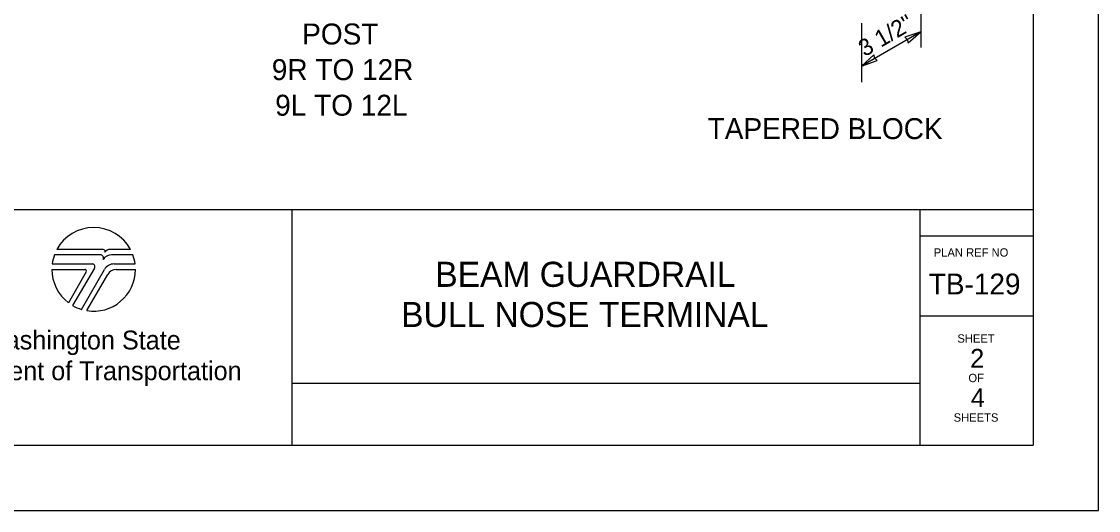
# Model space of a CAD drawing. Extents: x 1312564.2 to 1312581.5, y 1207298.4 to 1207352.6.
# Drawn here: x 1312576.33 to 1312581.48, y 1207312.82 to 1207315.16 of the extents above; entities that cross this region are included whole.
import ezdxf

# ---------------------------------------------------------------- set-up
doc = ezdxf.new("R2010")
doc.units = 0
for name, color, linetype in [('Level 1', 7, 'Continuous'), ('Level 15', 7, 'Continuous'), ('Level 2', 7, 'Continuous'), ('Level 20', 7, 'Continuous'), ('Level 36', 7, 'Continuous'), ('Level 63', 7, 'Continuous'), ('SH_GI_SheetTextInCells', 7, 'Continuous')]:
    doc.layers.add(name, color=color, linetype=linetype)

msp = doc.modelspace()

# ---------------------------------------------------------------- linework, layer by layer
at = {"layer": 'Level 1'}
for p, q in [((1312581.1655, 1207323.5084), (1312581.1655, 1207313.1334)), ((1312565.4155, 1207314.2593), (1312581.1655, 1207314.2593)), ((1312577.621, 1207314.2593), (1312577.621, 1207313.1334)), ((1312580.6233, 1207314.2593), (1312580.6233, 1207313.1334)), ((1312580.6233, 1207314.1342), (1312581.1655, 1207314.1342)), ((1312580.6233, 1207313.751), (1312581.1655, 1207313.751)), ((1312577.621, 1207313.4289), (1312580.6233, 1207313.4289)), ((1312565.4155, 1207313.1334), (1312581.1655, 1207313.1334))]:
    msp.add_line(p, q, dxfattribs=at)
at = {"layer": 'Level 15'}
for p, q in [((1312580.628, 1207315.3175), (1312580.628, 1207315.0345)), ((1312580.344, 1207315.1499), (1312580.344, 1207314.8684)), ((1312580.628, 1207315.1095), (1312580.344, 1207314.9455))]:
    msp.add_line(p, q, dxfattribs=at)
for points in [[(1312580.628, 1207315.1095), (1312580.5521, 1207315.0835), (1312580.563, 1207315.072), (1312580.5676, 1207315.0568)], [(1312580.344, 1207314.9455), (1312580.4199, 1207314.9715), (1312580.409, 1207314.9831), (1312580.4045, 1207314.9983)]]:
    msp.add_lwpolyline(points, close=True, dxfattribs=at)
at = {"layer": 'Level 2'}
msp.add_lwpolyline([(1312564.478, 1207312.8209), (1312581.478, 1207312.8209), (1312581.478, 1207323.8209), (1312564.478, 1207323.8209)], close=True, dxfattribs=at)
at = {"layer": 'Level 63'}
for p, q in [((1312576.7049, 1207314.0428), (1312576.4852, 1207314.0428)), ((1312576.7185, 1207314.0688), (1312576.497, 1207314.0688)), ((1312576.8485, 1207314.0688), (1312576.7506, 1207314.0688)), ((1312576.7585, 1207314.0428), (1312576.7584, 1207314.0428)), ((1312576.8603, 1207314.0428), (1312576.7585, 1207314.0428)), ((1312576.4745, 1207313.9994), (1312576.6651, 1207313.9994)), ((1312576.7713, 1207313.9994), (1312576.871, 1207313.9994)), ((1312576.4727, 1207313.9734), (1312576.6303, 1207313.9734)), ((1312576.6374, 1207313.9611), (1312576.5519, 1207313.8141)), ((1312576.6765, 1207313.9797), (1312576.5722, 1207313.8006)), ((1312576.6144, 1207313.7821), (1312576.7244, 1207313.9724)), ((1312576.6399, 1207313.7762), (1312576.7397, 1207313.949)), ((1312576.7809, 1207313.9728), (1312576.8727, 1207313.9728))]:
    msp.add_line(p, q, dxfattribs=at)
for centre, radius, start, end in [((1312576.6727, 1207313.9734), 0.2, 28.4787, 151.532), ((1312576.6727, 1207313.9734), 0.2, 159.696, 172.5057), ((1312576.7049, 1207314.028), 0.0148, 327.8418, 89.9985), ((1312576.7584, 1207313.9944), 0.0484, 89.9953, 147.8238), ((1312576.7184, 1207314.0597), 0.00903, 329.8742, 90.0033), ((1312576.7506, 1207314.04), 0.0287, 90.0072, 148.1676), ((1312576.6727, 1207313.9734), 0.2, 7.4943, 20.2941), ((1312576.6651, 1207313.9863), 0.0131, 329.7683, 90), ((1312576.7713, 1207313.9453), 0.0542, 90, 149.9974), ((1312576.6727, 1207313.9734), 0.2, 179.9986, 232.8433), ((1312576.6303, 1207313.9652), 0.0082, 329.7436, 90), ((1312576.6727, 1207313.9734), 0.2, 260.5455, 359.8086), ((1312576.7809, 1207313.9252), 0.0476, 90, 150.0543), ((1312576.6727, 1207313.9734), 0.2, 239.7929, 253.0448)]:
    msp.add_arc(centre, radius, start, end, dxfattribs=at)

# ---------------------------------------------------------------- texts
at = {"layer": 'Level 1'}
msp.add_text('PLAN REF NO', height=0.040032, dxfattribs=at).set_placement((1312580.6902, 1207314.0342))
at = {"layer": 'Level 15'}
for s, height, p in [('POST ', 0.10015, (1312577.6698, 1207315.0485)), ('9R TO 12R', 0.10015, (1312577.5246, 1207314.8782)), ('9L TO 12L', 0.10015, (1312577.5407, 1207314.708)), ('TAPERED BLOCK', 0.100147, (1312579.609, 1207314.5961))]:
    msp.add_text(s, height=height, dxfattribs=at).set_placement(p)
at = {"layer": 'Level 20'}
msp.add_text("3 1/2''", height=0.08012, rotation=30, dxfattribs=at).set_placement((1312580.3598, 1207314.9879))
for s, p in [('BEAM GUARDRAIL', (1312578.3064, 1207313.8898)), ('BULL NOSE TERMINAL', (1312578.1434, 1207313.6978))]:
    msp.add_text(s, height=0.12, dxfattribs=at).set_placement(p)
at = {"layer": 'Level 36'}
for s, height, p in [('TB-129', 0.1, (1312580.6666, 1207313.8534)), ('2', 0.09, (1312580.8645, 1207313.5032)), ('4', 0.09, (1312580.8679, 1207313.3152))]:
    msp.add_text(s, height=height, dxfattribs=at).set_placement(p)
at = {"layer": 'SH_GI_SheetTextInCells'}
for s, height, p in [('Washington State', 0.090072, (1312576.1384, 1207313.5905)), ('SHEET', 0.04003, (1312580.8032, 1207313.623)), ('Department of Transportation', 0.090072, (1312575.807, 1207313.4435)), ('OF', 0.04003, (1312580.8561, 1207313.4342)), ('SHEETS', 0.04003, (1312580.7853, 1207313.2453))]:
    msp.add_text(s, height=height, dxfattribs=at).set_placement(p)

doc.saveas('drawing.dxf')
